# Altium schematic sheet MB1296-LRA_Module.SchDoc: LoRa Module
size A4; Date: 18-AUG-2016; Organization: STMicroelectronics; Address1: Microcontrollers Division; Address2: 190, avenue Célestin COQ; Address3: 13106 ROUSSET Cedex; Address4: FRANCE; DocumentNumber: MB1296; Revision: C-01; SheetNumber: 4; SheetTotal: 6; Project: STM32 LoRa Discovery
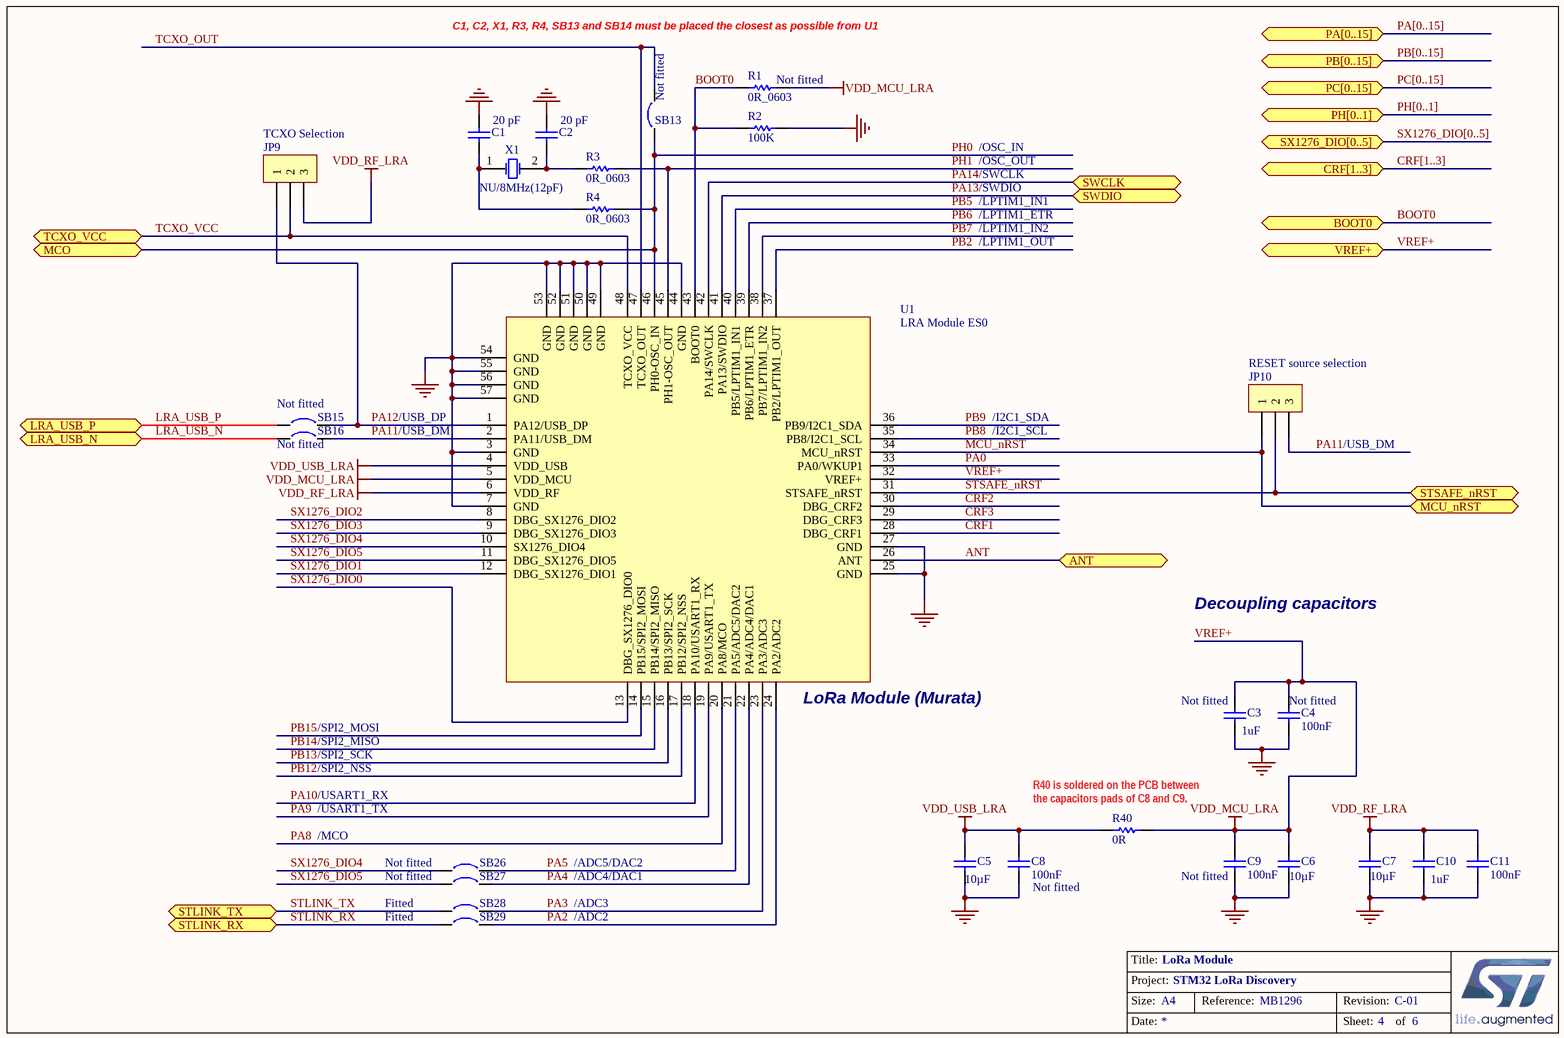
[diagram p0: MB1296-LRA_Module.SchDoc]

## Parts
C1  20 pF  [0603C]
C2  20 pF  [0603C]
C3  1uF  [0603C]
C4  100nF  [0603C]
C5  10µF  [0603C]
C6  10µF  [0603C]
C7  10µF  [0603C]
C8  100nF  [0603C]
C9  100nF  [0603C]
C10  1uF  [0603C]
C11  100nF  [0603C]
JP9  TCXO Selection  [SIP3]
JP10  RESET source selection  [SIP3]
R1  0R_0603  [0603]
R2  100K  [0603]
R3  0R_0603  [0603]
R4  0R_0603  [0603]
R40  0R  [0603]
SB13  Circuit Breaker  [JP2_SMD]  (value not drawn)
SB15  Circuit Breaker  [JP2_SMD]  (value not drawn)
SB16  Circuit Breaker  [JP2_SMD]  (value not drawn)
SB26  Circuit Breaker  [JP2_SMD]  (value not drawn)
SB27  Circuit Breaker  [JP2_SMD]  (value not drawn)
SB28  Circuit Breaker  [JP2_SMD]  (value not drawn)
SB29  Circuit Breaker  [JP2_SMD]  (value not drawn)
U1  LRA Module ES0  [Lora Module ES0]
X1  NU/8MHz(12pF)  [CRY_NX3225GD_2P]

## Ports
ANT, BOOT0, CRF[1..3], LRA_USB_N, LRA_USB_P, MCO, MCU_nRST, PA[0..15] (bidir), PB[0..15] (bidir), PC[0..15] (bidir), PH[0..1] (bidir), STLINK_RX, STLINK_TX, STSAFE_nRST, SWCLK, SWDIO, SX1276_DIO[0..5] (bidir), TCXO_VCC, VREF+

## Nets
GND: C1.2 C2.2 C3.1 C4.1 C5.2 C6.2 C7.2 C8.1 C9.1 C10.1 C11.1 R2.1 U1.3(GND) U1.7(GND) U1.25(GND) U1.27(GND) U1.44(GND) U1.49(GND) U1.50(GND) U1.51(GND) U1.52(GND) U1.53(GND) U1.54(GND) U1.55(GND) U1.56(GND) U1.57(GND)
VDD_RF_LRA: C7.1 C10.2 C11.2 JP9.3 U1.6(VDD_RF)
VDD_USB_LRA: C5.1 C8.2 R40.2 U1.4(VDD_USB)
VREF+: C3.2 C4.2 C6.1 C9.2 R1.2 R40.1 U1.5(VDD_MCU) U1.32(VREF+) ; port VREF+  [also labelled VDD_MCU_LRA]
ANT: U1.26(ANT) ; port ANT
BOOT0: R1.1 R2.2 U1.43(BOOT0) ; port BOOT0
CRF1: U1.28(DBG_CRF1)
CRF2: U1.30(DBG_CRF2)
CRF3: U1.29(DBG_CRF3)
LRA_USB_N: SB16.1 ; port LRA_USB_N
LRA_USB_P: SB15.1 ; port LRA_USB_P
MCU_nRST: JP10.1 U1.34(MCU_nRST) ; port MCU_nRST
PA0: U1.33(PA0/WKUP1)
PA2: SB29.2 U1.24(PA2/ADC2)
PA3: SB28.2 U1.23(PA3/ADC3)
PA4: SB27.2 U1.22(PA4/ADC4/DAC1)
PA5: SB26.2 U1.21(PA5/ADC5/DAC2)
PA8: U1.20(PA8/MCO)
PA9: U1.19(PA9/USART1_TX)
PA10: U1.18(PA10/USART1_RX)
PA11: JP10.3 SB16.2 U1.2(PA11/USB_DM)
PA12: JP9.1 SB15.2 U1.1(PA12/USB_DP)
PA13: U1.41(PA13/SWDIO) ; port SWDIO
PA14: U1.42(PA14/SWCLK) ; port SWCLK
PB2: U1.37(PB2/LPTIM1_OUT)
PB5: U1.40(PB5/LPTIM1_IN1)
PB6: U1.39(PB6/LPTIM1_ETR)
PB7: U1.38(PB7/LPTIM1_IN2)
PB8: U1.35(PB8/I2C1_SCL)
PB9: U1.36(PB9/I2C1_SDA)
PB12: U1.17(PB12/SPI2_NSS)
PB13: U1.16(PB13/SPI2_SCK)
PB14: U1.15(PB14/SPI2_MISO)
PB15: U1.14(PB15/SPI2_MOSI)
PH0: R4.2 SB13.1 U1.46(PH0-OSC_IN) ; port MCO
PH1: R3.2 U1.45(PH1-OSC_OUT)
STLINK_RX: SB29.1 ; port STLINK_RX
STLINK_TX: SB28.1 ; port STLINK_TX
STSAFE_nRST: JP10.2 U1.31(STSAFE_nRST) ; port STSAFE_nRST
SX1276_DIO0: U1.13(DBG_SX1276_DIO0)
SX1276_DIO1: U1.12(DBG_SX1276_DIO1)
SX1276_DIO2: U1.8(DBG_SX1276_DIO2)
SX1276_DIO3: U1.9(DBG_SX1276_DIO3)
SX1276_DIO4: SB26.1 U1.10(SX1276_DIO4)
SX1276_DIO5: SB27.1 U1.11(DBG_SX1276_DIO5)
TCXO_OUT: SB13.2 U1.47(TCXO_OUT)
TCXO_VCC: JP9.2 U1.48(TCXO_VCC) ; port TCXO_VCC
NetC1_1: C1.1 R4.1 X1.1(OSC1)
NetC2_1: C2.1 R3.1 X1.2(OSC2)

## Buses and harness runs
bus CRF[1..3] = port CRF[1..3]
bus PA[0..15] = port PA[0..15]
bus PB[0..15] = port PB[0..15]
bus PC[0..15] = port PC[0..15]
bus PH[0..1] = port PH[0..1]
bus SX1276_DIO[0..5] = port SX1276_DIO[0..5]

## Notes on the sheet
- C1, C2, X1, R3, R4, SB13 and SB14 must be placed the closest as possible from U1
- (near SB13) Not fitted
- (near R1) Not fitted
- /OSC_IN
- /OSC_OUT
- /SWCLK
- /SWDIO
- /LPTIM1_IN1
- /LPTIM1_ETR
- /LPTIM1_IN2
- /LPTIM1_OUT
- (near SB15) Not fitted
- (near SB16) Not fitted
- /USB_DP
- /USB_DM
- /I2C1_SDA
- /I2C1_SCL
- Decoupling capacitors
- (near U1) LoRa Module (Murata)
- (near C3) Not fitted
- (near C4) Not fitted
- /SPI2_MOSI
- /SPI2_MISO
- /SPI2_SCK
- /SPI2_NSS
- /USART1_RX
- /USART1_TX
- /MCO
- (near R40) R40 is soldered on the PCB between the capacitors pads of C8 and C9.
- (near SB26) Not fitted
- Not fitted
- Fitted
- /ADC5/DAC2
- /ADC4/DAC1
- /ADC3
- /ADC2
- (near C8) Not fitted
- (near C9) Not fitted

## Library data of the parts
C1 C2 = Capacitor_ST: Capacitor 0603; Manufacturer: YAGEO; Manufacturer P/N: CC0603JRNPO9BN200; Value: 20pF; Fitted: No; Provided by: Subcon
C3 = CAP SMD 0603  X5R 1µF 25V 10%: 0603  X5R 1µF; Manufacturer: YAGEO; Manufacturer P/N: CC0603KRX5R7BB105; Fitted: No; Provided by: Subcon
C4 C11 = CAP: Capacitor 100nF; Manufacturer: YAGEO; Manufacturer P/N: CC0603KRX7R9BB104; Fitted: No; Provided by: Subcon
C5-C7 = CAP_C0805C106K8RACTU: Capacitor SMD 0805 10000000pF X7R 10V +/-10%; Manufacturer: Kemet; Order code RS: ...; Tolerance: 10%; Fitted: Yes
C8 C9 = CAP: Capacitor 100nF; Manufacturer: YAGEO; Manufacturer P/N: CC0603KRX7R9BB104; Provided by: Subcon
C10 = CAP SMD 0603  X5R 1µF 25V 10%: 0603  X5R 1µF; Manufacturer: YAGEO; Manufacturer P/N: CC0603KRX5R7BB105; Provided by: Subcon
JP9 JP10 = Header 3: Manufacturer: Kontek; Manufacturer P/N: 4710334140400; Order Code RS: 423-2835; Provided by: Subcon
R1 = RES SMD 0603 0R 50V 0.1W: 0603 0R 50V 0.1W; Manufacturer: YAGEO; Manufacturer P/N: RC0603JR-070RL; Order code RS: 6555461; Fitted: No
R2 R40 = RES SMD 0603 100K 75V 5% 0.1W: 0603 100K 75V 5% 0.1W; Manufacturer: YAGEO; Manufacturer P/N: RC0603FR-07100KL; Provided by: Subcon
R3 R4 = RES SMD 0603 0R 50V 0.1W: 0603 0R 50V 0.1W; Manufacturer: YAGEO; Manufacturer P/N: RC0603JR-070RL; Order code RS: 6555461
SB13 SB15 SB16 SB26 SB27 = Circuit Breaker: Fitted: No
SB28 SB29 = Circuit Breaker: Fitted: Yes
U1 = LRA Module ES0: Manufacturer: Murata
X1 = XTAL: Crystal Oscillator; Manufacturer: HongKongCrystal; Manufacturer P/N: 9SL8000012AFXHF0-SJ28; Fitted: No; Provided by: Subcon; Value: 8MHz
